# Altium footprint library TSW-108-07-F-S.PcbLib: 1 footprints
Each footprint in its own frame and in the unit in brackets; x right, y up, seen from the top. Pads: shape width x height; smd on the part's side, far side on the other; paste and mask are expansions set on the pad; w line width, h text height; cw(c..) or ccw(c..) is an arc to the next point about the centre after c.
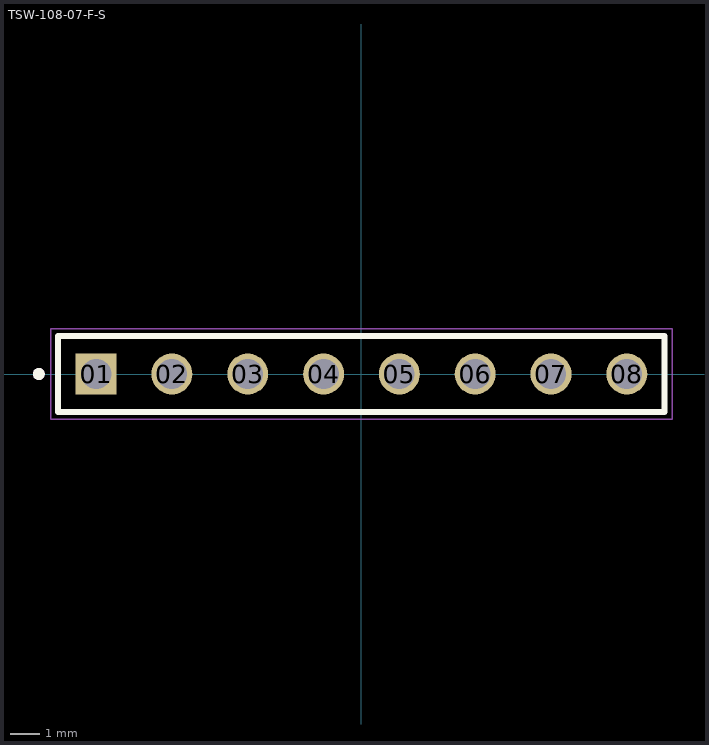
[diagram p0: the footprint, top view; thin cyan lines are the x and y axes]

## TSW-108-07-F-S [mm]
pads (8):
  rect 1.37x1.37 hole 1.02: 01(-8.89,0)
  round 1.37 hole 1.02: 02(-6.35,0) 03(-3.81,0) 04(-1.27,0) 05(1.27,0) 06(3.81,0) 07(6.35,0) 08(8.89,0)
Top Overlay:
  circle w0.2: c-10.81,0 r0.1
  lines w0.2: -10.16,-1.27 -10.16,1.27 10.16,1.27 10.16,-1.27 -10.16,-1.27
Mechanical 13:
  circle w0.2: c-10.81,0 r0.1
  lines w0.1: -10.16,-1.27 -10.16,1.27 ; -10.16,-1.27 10.16,-1.27 ; -10.16,-1.27 -10.16,1.27 ; -10.16,1.27 10.16,1.27 ; -10.16,1.27 10.16,1.27 ; 10.16,-1.27 10.16,1.27 ; 10.16,-1.27 10.16,1.27
Mechanical 15:
  lines w0.05: -10.41,-1.52 -10.41,1.52 10.41,1.52 10.41,-1.52 -10.41,-1.52
3D body "TSW-108-07-F-S.stp": height 8.38, standoff -2.54, extent -10.16,-1.27 10.287,1.27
